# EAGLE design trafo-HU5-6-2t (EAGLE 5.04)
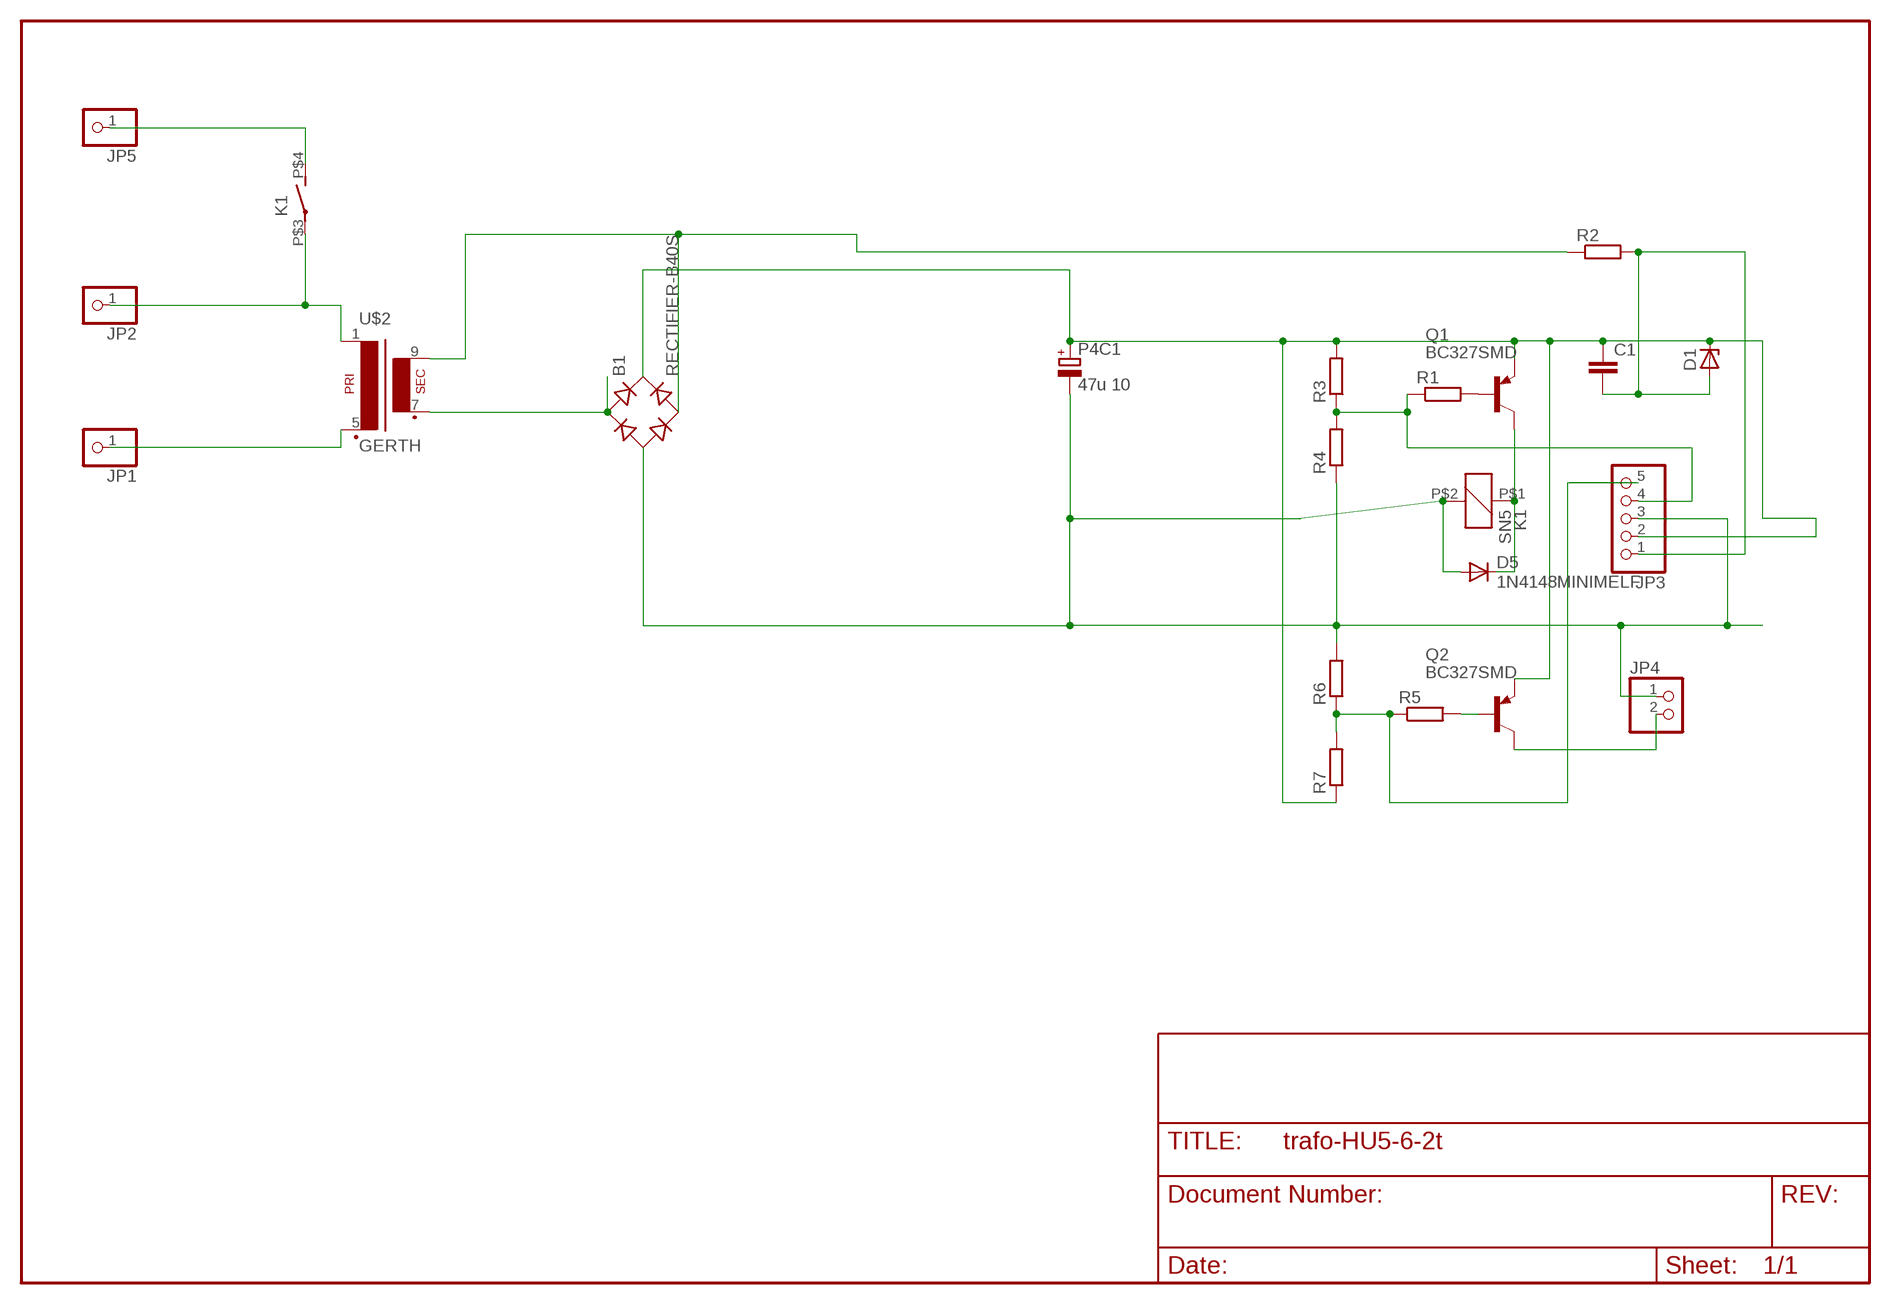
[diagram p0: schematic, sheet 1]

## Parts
B1  RECTIFIER-B40S  [B40S]
C1  C-EUC1206  [C1206]
D1  ZENER-DIODESOT23  [SOT23]
D5  1N4148MINIMELF  [MINIMELF]
JP1  PINHD-1X1  [1X01]
JP2  PINHD-1X1  [1X01]
JP3  PINHD-1X5  [1X05]
JP4  PINHD-1X2  [1X02]
JP5  PINHD-1X1  [1X01]
K1  SN5  [HU]
P4C1  47u 10  CPOL-EUE2-5  [E2-5]
Q1  BC327SMD  [SOT23-BEC]
Q2  BC327SMD  [SOT23-BEC]
R1  R-EU_R0805  [R0805]
R2  R-EU_R0805  [R0805]
R3  R-EU_R0805  [R0805]
R4  R-EU_R0805  [R0805]
R5  R-EU_R0805  [R0805]
R6  R-EU_R1206  [R1206]
R7  R-EU_R0805  [R0805]
U$2  GERTH  [150.06]

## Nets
N$1: JP2.1 K1.P$3(2:P) U$2.1
N$2: B1.+ C1.1 D1.3(C) JP3.2 P4C1.+ Q1.E Q2.E R3.2 R7.1
N$3: B1.- D5.A JP3.3 JP4.1 K1.P$2 P4C1.- R4.1 R6.2
N$4: JP5.1 K1.P$4(2:S)
N$5: JP1.1 U$2.5(P2)
N$6: B1.AC1 U$2.7(S3)
N$7: B1.AC2 R2.1 U$2.9(S4)
N$8: Q1.B R1.2
N$9: C1.2 D1.1(A) JP3.1 R2.2
N$10: JP3.4 R1.1 R3.1 R4.2
N$11: D5.C K1.P$1 Q1.C
N$12: JP4.2 Q2.C
N$13: JP3.5 R5.1 R6.1 R7.2
N$15: Q2.B R5.2

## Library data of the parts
B1 = rectifier:RECTIFIER-: Rectifier
C1 = rcl-2:C-EU: CAPACITOR, European symbol
D1 = diode-1:ZENER-DIODE: Z-Diode
D5 = diode-1:1N4148: DIODE
JP1 JP2 JP5 = pinhead(2):PINHD-1X1: PIN HEADER
JP3 = pinhead:PINHD-1X5: PIN HEADER
JP4 = pinhead:PINHD-1X2: PIN HEADER
K1 = relay:SN*: Slim PCB Relay 1 pole 6 A SCHRACK Source: http://www.schrack.com/.. 5815.pdf
P4C1 = rcl:CPOL-EU: POLARIZED CAPACITOR, European symbol
Q1 Q2 = transistor-pnp:BC327*: PNP Transistror
R1-R7 = rcl-2:R-EU_: RESISTOR, European symbol
U$2 = trafo:GERTH

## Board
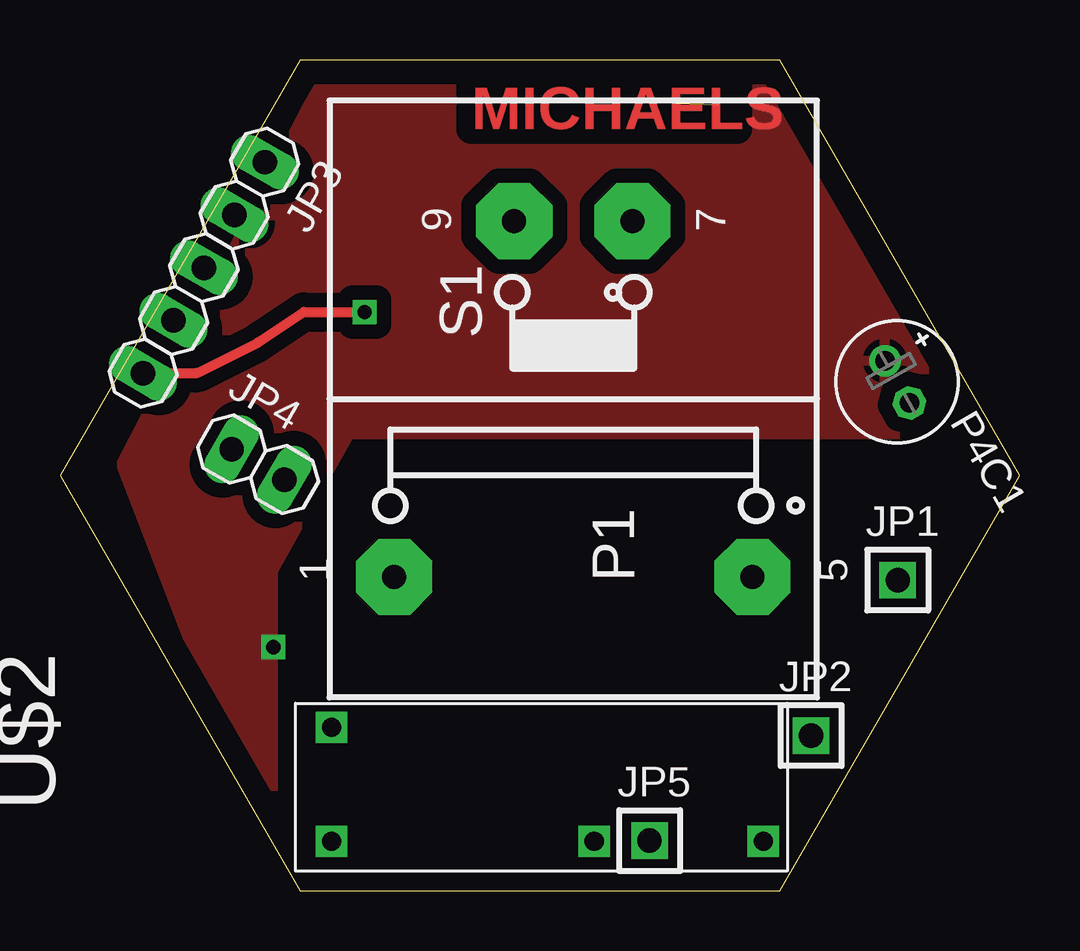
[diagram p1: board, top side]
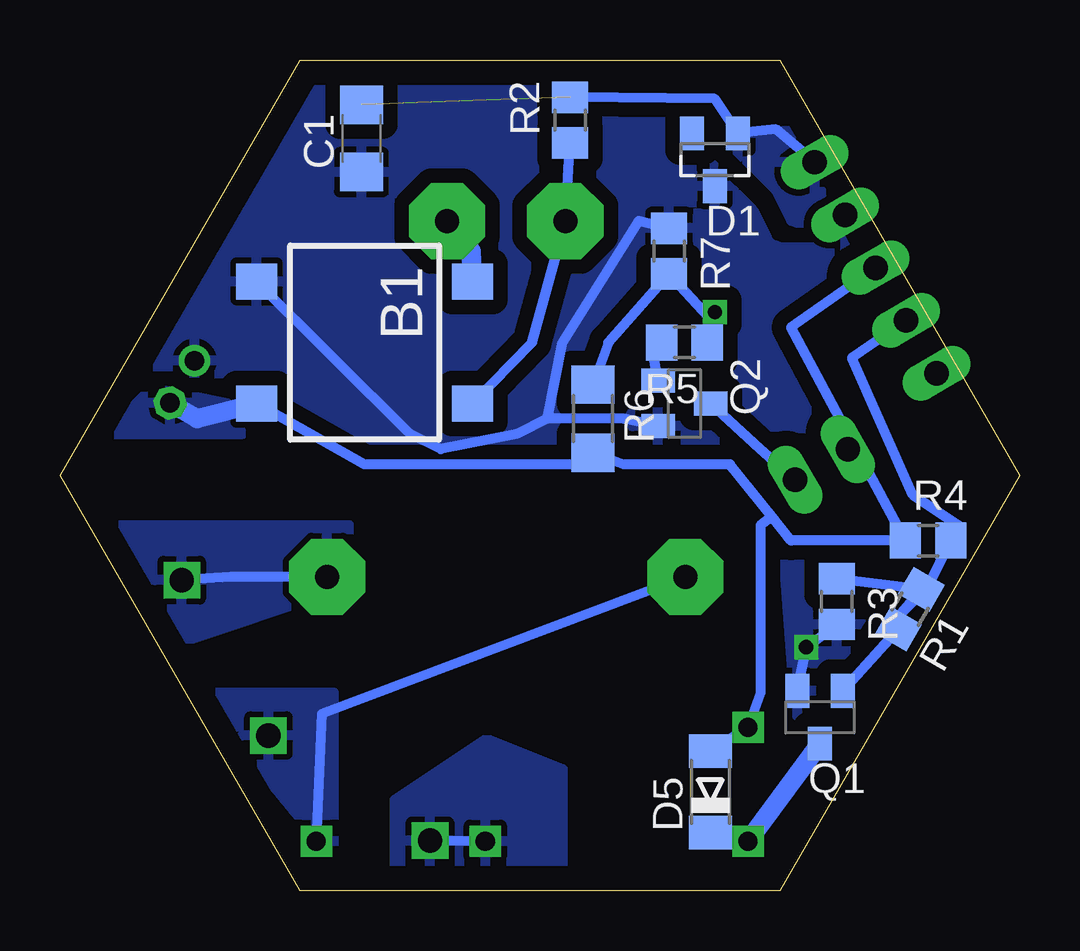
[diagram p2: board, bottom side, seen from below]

Size 40 x 34.64 mm. Coordinates in mm from the lower left corner, seen from the top.
Outline: 10,0 30,0 40,17.32 30,34.64 10,34.64 0,17.32 10,0
Copper layers (1*16): Top 0.035mm / dielectric 1.5mm / Bottom 0.035mm
Design rules "default": minimum track width 10mil, minimum drill 24mil, track to track 8mil, track to pad 8mil, pad to pad 8mil, via to via 8mil, smd to smd 8mil, copper to edge 40mil, drill to drill 8mil, minimum pad ring 10mil, minimum via ring 8mil, stop-mask expansion 4mil, vias tented up to drill 0mil, thermal gap 10mil

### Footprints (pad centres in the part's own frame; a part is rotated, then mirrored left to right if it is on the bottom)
B40S = smd 1.5 x 1.7: + -2.55,-4.5; - 2.55,-4.5; AC1 -2.55,4.5; AC2 2.55,4.5
C1206 = smd 1.6 x 1.8: 1 -1.4,0; 2 1.4,0
SOT23 = smd 1 x 1.4: 1 -0.95,-1.1; 2 0.95,-1.1; 3 0,1.1
MINIMELF = smd 1.4 x 1.8: A 1.7,0; C -1.7,0
1X01 = drill 1.016 square: 1 0,0
1X05 = drill 1.016 long: 1 -5.08,0; 2 -2.54,0; 3 0,0; 4 2.54,0; 5 5.08,0
1X02 = drill 1.016 long: 1 -1.27,0; 2 1.27,0
HU = drill 0.8 square: P$1 2.25,-9; P$2 -2.5,-9; P$3 2.25,9; P$4 2.25,1.95
E2-5 = drill 0.813 pad 1.27 round: + -1.016,0 | drill 0.813 pad 1.27 octagon: - 1.016,0
SOT23-BEC = smd 1 x 1.4: B -0.95,-1.1; C 0,1.1; E 0.95,-1.1
R0805 = smd 1.3 x 1.5: 1 -0.95,0; 2 0.95,0
R1206 = smd 1.6 x 1.803: 1 -1.422,0; 2 1.422,0
150.06 = drill 1 pad 3.175 octagon: 1 -7.417,7.468; 5 -7.417,-7.468; 7 7.417,-2.464; 9 7.417,2.464

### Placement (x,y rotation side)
B1  27.3,22.86 270 bottom
C1  27.43,31.37 90 bottom
D1  12.7,30.48 180 bottom
D5  12.89,4.13 90 bottom
JP1  34.92,12.95 0 top
JP2  31.31,6.48 0 top
JP3  6,25.98 240 top
JP4  8.26,17.78 330 top
JP5  24.57,2.1 0 top
K1  20.32,4.32 270 top
P4C1  34.9,21.22 300 top
Q1  8.32,7.24 180 bottom
Q2  13.97,20.32 270 bottom
R1  4.56,11.75 240 bottom
R2  18.73,32.13 90 bottom
R3  7.62,12.06 270 bottom
R4  3.81,14.61 0 bottom
R5  13.97,22.86 180 bottom
R6  17.78,19.68 270 bottom
R7  14.61,26.67 270 bottom
U$2  21.4,20.51 90 top

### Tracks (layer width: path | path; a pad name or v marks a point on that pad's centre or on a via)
N$1
  Bottom 0.406: U$2.1 29.09,7.38 K1.P$3
  pour Bottom (isolate 0.61, rank 2): 28.57,1.27 28.57,8.26 34.29,8.26
N$2  (via drill 0.6)
  Bottom 0.406: Q1.E v8.89,10.16 R3.2 | Q2.E 16.51,19.68 19.68,19.68 | 19.68,19.68 19.05,22.86 15.88,27.94 R7.1 | B1.+ 25.4,19.05 24.13,18.41 20.95,19.05 19.68,19.68
  pour Top (isolate 0.61, rank 3): 2.54,17.78 8.89,1.27 8.89,13.34 12.06,19.05 38.1,19.05 29.21,33.66 10.79,33.66
  pour Bottom (isolate 0.61, rank 3): 2.54,17.78 8.89,1.27 10.16,18.41 38.1,18.41 29.21,33.66 10.79,33.66
N$3
  Bottom 0.406: B1.- 27.3,17.78 18.41,17.78 R6.2 16.51,17.78 12.06,17.78 10.33,15.61 | 10.33,15.61 9.53,14.61 R4.1 6.72,18.26 | 6.72,18.26 9.53,23.5 JP3.3 | D5.A K1.P$2 10.79,8.26 10.79,15.24 10.33,15.61 | JP4.1 6.72,18.41 6.72,18.26
  Bottom 0.813: B1.- 34.29,19.68 P4C1.-
  pour Bottom (isolate 0.305): 33.02,20.32 36.2,20.95 38.1,19.05 32.38,19.05
N$4
  Bottom 0.406: K1.P$4 JP5.1
  pour Bottom: 26.04,0.64 26.04,3.81 22.23,6.35 19.05,5.08 19.05,0.64
N$5
  Bottom 0.406: U$2.5 32.88,13.09 JP1.1
  pour Bottom (isolate 0.61, rank 2): 27.94,15.24 38.1,15.24 35.56,10.16 27.94,12.7
N$6
  Bottom 0.813: B1.AC1 22.86,26.67 U$2.7
N$7
  Bottom 0.406: R2.1 U$2.9 20.32,22.86 B1.AC2
N$8
  Bottom 0.406: R1.2 Q1.B
N$9  (1 unrouted)
  Bottom 0.406: JP3.1 10.16,31.75 D1.1 12.7,33.02 R2.2
  pour Bottom (isolate 0.305): 6.35,26.67 9.53,31.75 12.06,31.11 10.16,29.21 9.53,27.94
N$10
  Bottom 0.406: JP3.4 6.99,22.23 4.45,16.51 2.54,15.24 3.81,12.7 | 3.81,12.7 5.08,11.43 R1.1 R3.1 | 3.81,12.7 R4.2
N$11
  Bottom 0.406: K1.P$1 D5.C
  Bottom 0.813: K1.P$1 Q1.C
N$12
  Bottom 0.406: JP4.2 10.79,18.41 Q2.C
N$13  (via drill 0.6)
  Top 0.406: JP3.5 5.71,21.59 8.26,22.86 10.16,24.13 v12.7,24.13
  Bottom 0.406: R6.1 17.14,22.86 R7.2 12.73,23.68 | R5.1 12.7,23.5 12.73,23.68 | v12.7,24.13 12.73,23.68
N$15
  Bottom 0.406: Q2.B 15.24,22.23 R5.2

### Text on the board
Top: MICHAELS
